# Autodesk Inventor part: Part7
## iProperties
Shininess: 77.0
Angle Display Precision: 2
Document Length Units: 11269
Document Angle Units: 11279
Document Time Units: 11290
Document Mass Units: 11283
Document Length Units Precision: 3
Document Angle Units Precision: 2
Compacted: True
Created: 2002-04
Part Number: Part7
Document SubType Name: Sheet Metal
Density: 0.0
Volumn: 0.0
Area: 0.0
PropertySet Name: Model Information
Control State: 0
Master: False
Checked Out: False
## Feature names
1. Plate1
2. Plate3
3. Bend2
4. Plate4
5. Bend3
